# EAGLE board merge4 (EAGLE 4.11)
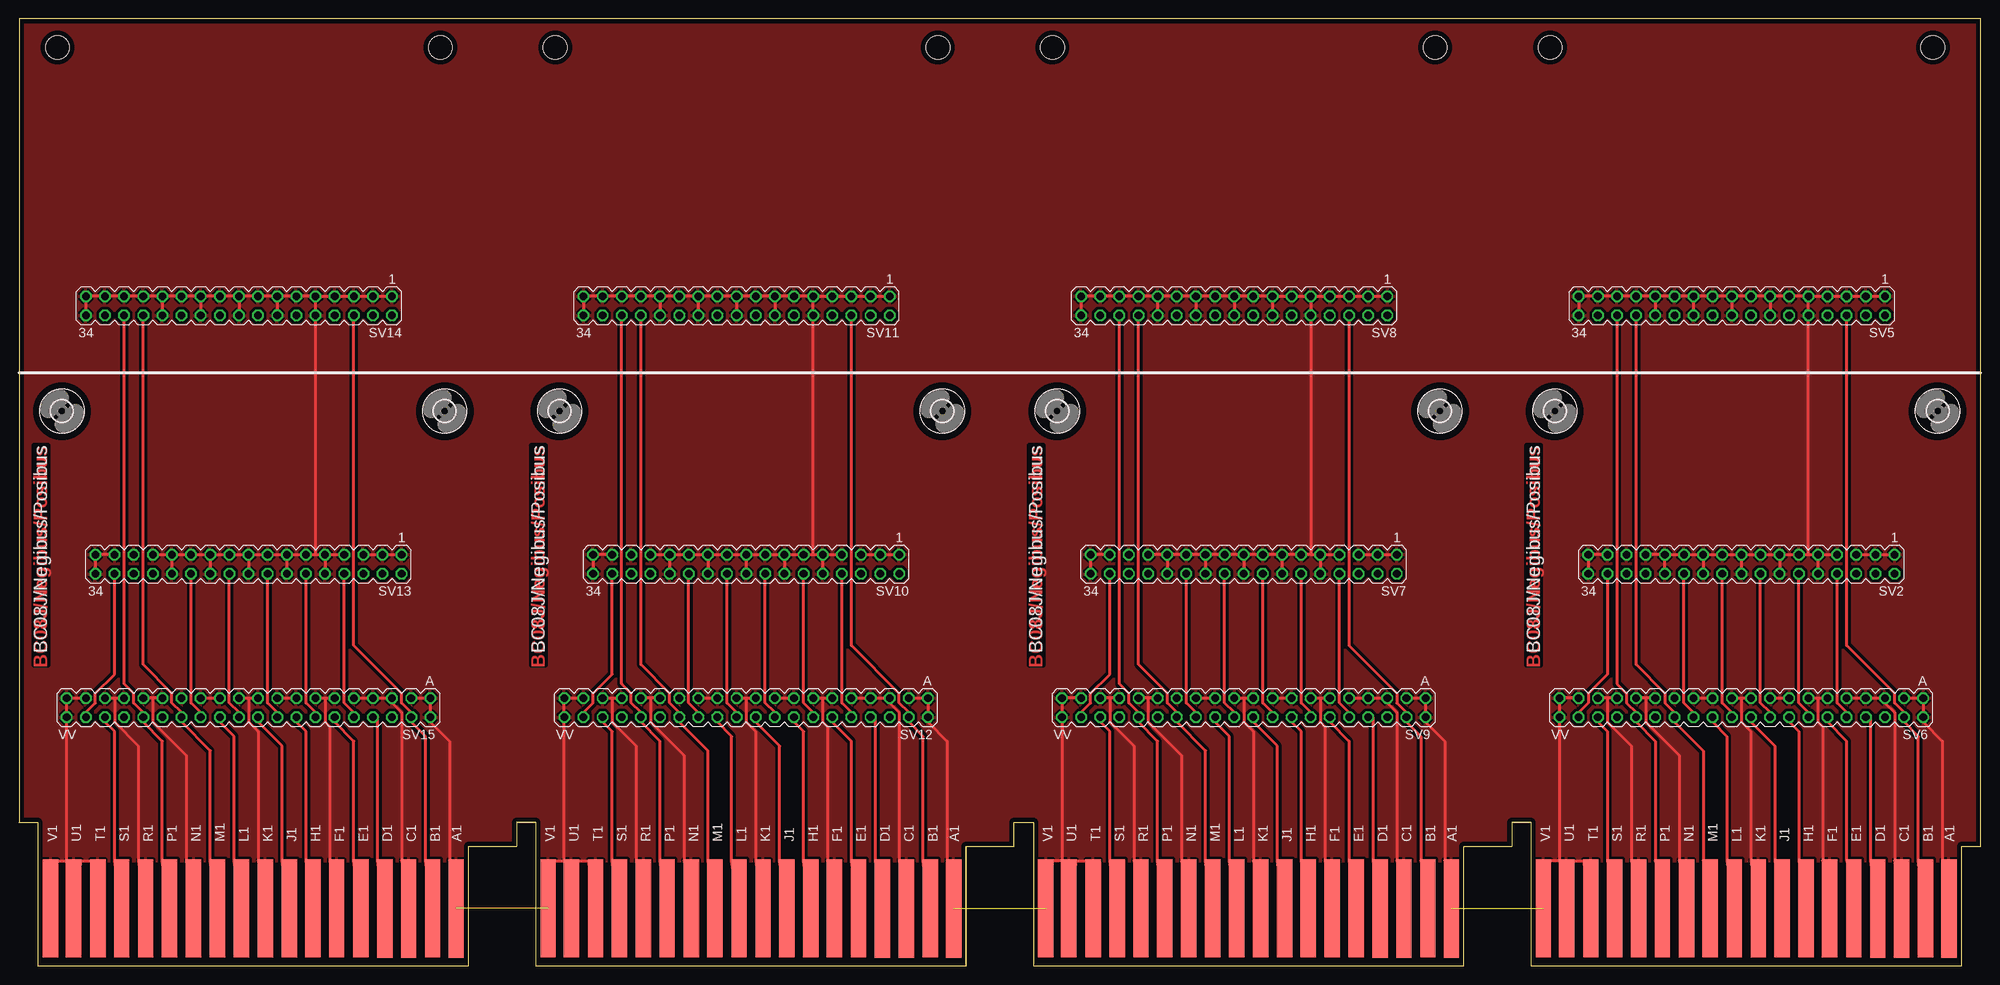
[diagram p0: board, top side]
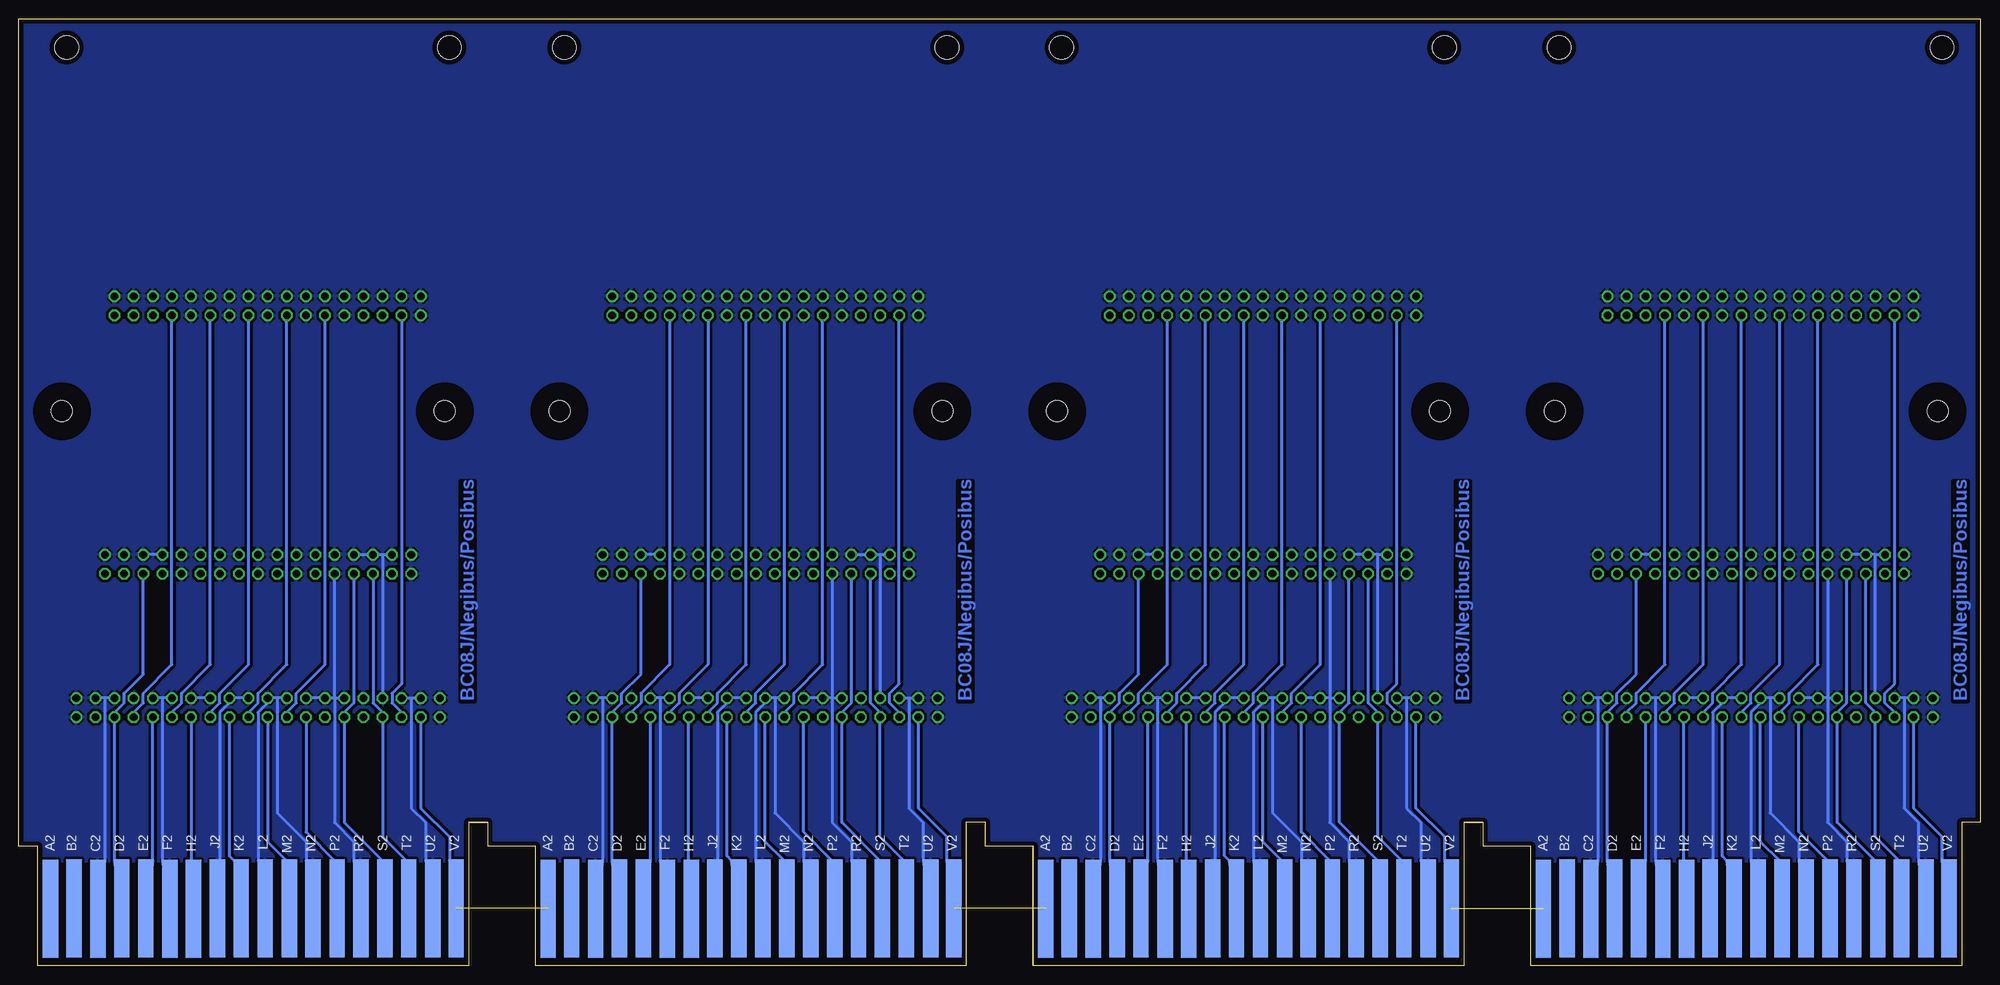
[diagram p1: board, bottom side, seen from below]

Size 260.35 x 125.73 mm. Coordinates in mm from the lower left corner, seen from the top.
Copper layers (1*16): Top 0.035mm / dielectric 1.5mm / Bottom 0.035mm
Design rules "olimex10mil": minimum track width 15mil, minimum drill 24mil, track to track 15mil, track to pad 10mil, pad to pad 10mil, via to via 10mil, smd to smd 10mil, copper to edge 25mil, drill to drill 10mil, minimum pad ring 10mil, minimum via ring 8mil, stop-mask expansion 0mil, vias tented up to drill 0mil, thermal gap 10mil

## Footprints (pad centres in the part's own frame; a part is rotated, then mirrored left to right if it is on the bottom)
MA17-2 = drill 1.016 octagon: 1 -20.32,-1.27; 2 -20.32,1.27; 3 -17.78,-1.27; 4 -17.78,1.27; 5 -15.24,-1.27; 6 -15.24,1.27; 7 -12.7,-1.27; 8 -12.7,1.27; 9 -10.16,-1.27; 10 -10.16,1.27; 11 -7.62,-1.27; 12 -7.62,1.27; 13 -5.08,-1.27; 14 -5.08,1.27; 15 -2.54,-1.27; 16 -2.54,1.27; 17 0,-1.27; 18 0,1.27; 19 2.54,-1.27; 20 2.54,1.27; 21 5.08,-1.27; 22 5.08,1.27; 23 7.62,-1.27; 24 7.62,1.27; 25 10.16,-1.27; 26 10.16,1.27; 27 12.7,-1.27; 28 12.7,1.27; 29 15.24,-1.27; 30 15.24,1.27; 31 17.78,-1.27; 32 17.78,1.27; 33 20.32,-1.27; 34 20.32,1.27
DEC40PIN = drill 1.016 octagon: A -24.13,-1.27; AA 3.81,-1.27; B -24.13,1.27; BB 3.81,1.27; C -21.59,-1.27; CC 6.35,-1.27; D -21.59,1.27; DD 6.35,1.27; E -19.05,-1.27; EE 8.89,-1.27; F -19.05,1.27; FF 8.89,1.27; H -16.51,-1.27; HH 11.43,-1.27; J -16.51,1.27; JJ 11.43,1.27; K -13.97,-1.27; KK 13.97,-1.27; L -13.97,1.27; LL 13.97,1.27; M -11.43,-1.27; MM 16.51,-1.27; N -11.43,1.27; NN 16.51,1.27; P -8.89,-1.27; PP 19.05,-1.27; R -8.89,1.27; RR 19.05,1.27; S -6.35,-1.27; SS 21.59,-1.27; T -6.35,1.27; TT 21.59,1.27; U -3.81,-1.27; UU 24.13,-1.27; V -3.81,1.27; VV 24.13,1.27; W -1.27,-1.27; X -1.27,1.27; Y 1.27,-1.27; Z 1.27,1.27
DECPROTO = hole 3.175: 203.2,121.92; 254,121.92; 187.96,121.92; 137.16,121.92; 71.171,121.92; 121.971,121.92; 55.931,121.92; 5.131,121.92
EDGE-CON2 = smd 13.017 x 2.032: A1 7.633,4.207; B1 7.639,7.327; C1 7.636,10.489; D1 7.633,13.665; E1 7.642,16.84; F1 7.642,20.041; H1 7.642,23.19; J1 7.642,26.34; K1 7.642,29.515; L1 7.642,32.69; M1 7.642,35.89; N1 7.642,39.04; P1 7.642,42.24; R1 7.642,45.39; S1 7.642,48.565; T1 7.642,51.74; U1 7.642,54.966; V1 7.642,58.026 | smd 13.017 x 2.032 bottom: A2 7.614,4.207; B2 7.642,7.328; C2 7.617,10.49; D2 7.642,13.665; E2 7.642,16.84; F2 7.617,20.041; H2 7.617,23.19; J2 7.642,26.34; K2 7.642,29.515; L2 7.642,32.69; M2 7.642,35.89; N2 7.642,39.04; P2 7.642,42.24; R2 7.642,45.39; S2 7.642,48.565; T2 7.642,51.74; U2 7.642,54.966; V2 7.642,58.026
2,8 = hole 2.8: 0,0

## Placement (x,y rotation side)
SV2  [MA17-2]  228.6,53.34 180 top
SV5  [MA17-2]  227.33,87.63 180 top
SV6  [DEC40PIN]  228.6,34.29 180 top
SV7  [MA17-2]  162.56,53.34 180 top
SV8  [MA17-2]  161.29,87.63 180 top
SV9  [DEC40PIN]  162.56,34.29 180 top
SV10  [MA17-2]  96.52,53.34 180 top
SV11  [MA17-2]  95.25,87.63 180 top
SV12  [DEC40PIN]  96.52,34.29 180 top
SV13  [MA17-2]  30.48,53.34 180 top
SV14  [MA17-2]  29.21,87.63 180 top
SV15  [DEC40PIN]  30.48,34.29 180 top
U$5  DECPROTO  [DECPROTO]  0,0 0 top
U$6  [EDGE-CON2]  260.35,0 90 top
U$8  [2,8]  254.63,73.66 270 top
U$9  [2,8]  203.84,73.66 270 top
U$10  [EDGE-CON2]  194.31,0 90 top
U$12  [2,8]  188.59,73.66 270 top
U$13  [2,8]  137.79,73.66 270 top
U$14  [EDGE-CON2]  128.27,0 90 top
U$16  [2,8]  122.56,73.66 270 top
U$17  [2,8]  71.75,73.66 270 top
U$18  [EDGE-CON2]  62.23,0 90 top
U$20  [2,8]  56.52,73.66 270 top
U$21  [2,8]  5.71,73.66 270 top

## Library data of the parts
SV2 SV5 SV7 SV8 SV10 SV11 SV13 SV14 = con-lstb
SV6 SV9 SV12 SV15 U$5 U$6 U$10 U$14 U$18 = dec-con
U$8 U$9 U$12 U$13 U$16 U$17 U$20 U$21 = holes

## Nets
-15V1: U$6.B2
-15V2: U$10.B2
-15V3: U$14.B2
-15V4: U$18.B2
B2: SV5.6 SV6.D U$6.B1
B3: SV8.6 SV9.D U$10.B1
B4: SV11.6 SV12.D U$14.B1
B5: SV14.6 SV15.D U$18.B1
D3: SV2.6 SV6.F U$6.D2
D4: SV5.8 SV6.J U$6.D1
D5: SV7.6 SV9.F U$10.D2
D6: SV8.8 SV9.J U$10.D1
D7: SV10.6 SV12.F U$14.D2
D8: SV11.8 SV12.J U$14.D1
D9: SV13.6 SV15.F U$18.D2
D10: SV14.8 SV15.J U$18.D1
E3: SV2.8 SV6.L U$6.E2
E4: SV5.12 SV6.N U$6.E1
E5: SV7.8 SV9.L U$10.E2
E6: SV8.12 SV9.N U$10.E1
E7: SV10.8 SV12.L U$14.E2
E8: SV11.12 SV12.N U$14.E1
E9: SV13.8 SV15.L U$18.E2
E10: SV14.12 SV15.N U$18.E1
GND: SV2.1 SV2.3 SV2.5 SV2.7 SV2.9 SV2.10 SV2.11 SV2.13 SV2.14 SV2.15 SV2.17 SV2.18 SV2.19 SV2.21 SV2.22 SV2.23 SV2.25 SV2.26 SV2.27 SV2.29 SV2.31 SV2.33 SV2.34 SV5.1 SV5.3 SV5.5 SV5.7 SV5.9 SV5.10 SV5.11 SV5.13 SV5.14 SV5.15 SV5.17 SV5.18 SV5.19 SV5.21 SV5.22 SV5.23 SV5.25 SV5.26 SV5.27 SV5.29 SV5.31 SV5.33 SV5.34 SV6.A SV6.AA SV6.B SV6.C SV6.CC SV6.E SV6.EE SV6.H SV6.HH SV6.K SV6.KK SV6.M SV6.MM SV6.P SV6.PP SV6.S SV6.SS SV6.U SV6.UU SV6.VV SV6.W SV6.Y SV7.1 SV7.3 SV7.5 SV7.7 SV7.9 SV7.10 SV7.11 SV7.13 SV7.14 SV7.15 SV7.17 SV7.18 SV7.19 SV7.21 SV7.22 SV7.23 SV7.25 SV7.26 SV7.27 SV7.29 SV7.31 SV7.33 SV7.34 SV8.1 SV8.3 SV8.5 SV8.7 SV8.9 SV8.10 SV8.11 SV8.13 SV8.14 SV8.15 SV8.17 SV8.18 SV8.19 SV8.21 SV8.22 SV8.23 SV8.25 SV8.26 SV8.27 SV8.29 SV8.31 SV8.33 SV8.34 SV9.A SV9.AA SV9.B SV9.C SV9.CC SV9.E SV9.EE SV9.H SV9.HH SV9.K SV9.KK SV9.M SV9.MM SV9.P SV9.PP SV9.S SV9.SS SV9.U SV9.UU SV9.VV SV9.W SV9.Y SV10.1 SV10.3 SV10.5 SV10.7 SV10.9 SV10.10 SV10.11 SV10.13 SV10.14 SV10.15 SV10.17 SV10.18 SV10.19 SV10.21 SV10.22 SV10.23 SV10.25 SV10.26 SV10.27 SV10.29 SV10.31 SV10.33 SV10.34 SV11.1 SV11.3 SV11.5 SV11.7 SV11.9 SV11.10 SV11.11 SV11.13 SV11.14 SV11.15 SV11.17 SV11.18 SV11.19 SV11.21 SV11.22 SV11.23 SV11.25 SV11.26 SV11.27 SV11.29 SV11.31 SV11.33 SV11.34 SV12.A SV12.AA SV12.B SV12.C SV12.CC SV12.E SV12.EE SV12.H SV12.HH SV12.K SV12.KK SV12.M SV12.MM SV12.P SV12.PP SV12.S SV12.SS SV12.U SV12.UU SV12.VV SV12.W SV12.Y SV13.1 SV13.3 SV13.5 SV13.7 SV13.9 SV13.10 SV13.11 SV13.13 SV13.14 SV13.15 SV13.17 SV13.18 SV13.19 SV13.21 SV13.22 SV13.23 SV13.25 SV13.26 SV13.27 SV13.29 SV13.31 SV13.33 SV13.34 SV14.1 SV14.3 SV14.5 SV14.7 SV14.9 SV14.10 SV14.11 SV14.13 SV14.14 SV14.15 SV14.17 SV14.18 SV14.19 SV14.21 SV14.22 SV14.23 SV14.25 SV14.26 SV14.27 SV14.29 SV14.31 SV14.33 SV14.34 SV15.A SV15.AA SV15.B SV15.C SV15.CC SV15.E SV15.EE SV15.H SV15.HH SV15.K SV15.KK SV15.M SV15.MM SV15.P SV15.PP SV15.S SV15.SS SV15.U SV15.UU SV15.VV SV15.W SV15.Y U$6.A1 U$6.C1 U$6.C2 U$6.F1 U$6.F2 U$6.J2 U$6.K1 U$6.L2 U$6.N1 U$6.N2 U$6.R1 U$6.R2 U$6.T1 U$6.U1 U$6.U2 U$6.V1 U$10.A1 U$10.C1 U$10.C2 U$10.F1 U$10.F2 U$10.J2 U$10.K1 U$10.L2 U$10.N1 U$10.N2 U$10.R1 U$10.R2 U$10.T1 U$10.U1 U$10.U2 U$10.V1 U$14.A1 U$14.C1 U$14.C2 U$14.F1 U$14.F2 U$14.J2 U$14.K1 U$14.L2 U$14.N1 U$14.N2 U$14.R1 U$14.R2 U$14.T1 U$14.U1 U$14.U2 U$14.V1 U$18.A1 U$18.C1 U$18.C2 U$18.F1 U$18.F2 U$18.J2 U$18.K1 U$18.L2 U$18.N1 U$18.N2 U$18.R1 U$18.R2 U$18.T1 U$18.U1 U$18.U2 U$18.V1
H3: SV2.12 SV6.R U$6.H2
H4: SV5.16 SV6.T U$6.H1
H5: SV7.12 SV9.R U$10.H2
H6: SV8.16 SV9.T U$10.H1
H7: SV10.12 SV12.R U$14.H2
H8: SV11.16 SV12.T U$14.H1
H9: SV13.12 SV15.R U$18.H2
H10: SV14.16 SV15.T U$18.H1
J2: SV5.20 SV6.X U$6.J1
J3: SV8.20 SV9.X U$10.J1
J4: SV11.20 SV12.X U$14.J1
J5: SV14.20 SV15.X U$18.J1
K1: SV2.16 SV6.V U$6.K2
K3: SV7.16 SV9.V U$10.K2
K4: SV10.16 SV12.V U$14.K2
K5: SV13.16 SV15.V U$18.K2
L2: SV5.24 SV6.BB U$6.L1
L3: SV8.24 SV9.BB U$10.L1
L4: SV11.24 SV12.BB U$14.L1
L5: SV14.24 SV15.BB U$18.L1
M3: SV2.20 SV6.Z U$6.M2
M4: SV5.28 SV6.FF U$6.M1
M5: SV7.20 SV9.Z U$10.M2
M6: SV8.28 SV9.FF U$10.M1
M7: SV10.20 SV12.Z U$14.M2
M8: SV11.28 SV12.FF U$14.M1
M9: SV13.20 SV15.Z U$18.M2
M10: SV14.28 SV15.FF U$18.M1
P3: SV2.24 SV6.DD U$6.P2
P4: SV5.30 SV6.LL U$6.P1
P5: SV7.24 SV9.DD U$10.P2
P6: SV8.30 SV9.LL U$10.P1
P7: SV10.24 SV12.DD U$14.P2
P8: SV11.30 SV12.LL U$14.P1
P9: SV13.24 SV15.DD U$18.P2
P10: SV14.30 SV15.LL U$18.P1
S3: SV2.28 SV6.JJ U$6.S2
S4: SV5.32 SV6.RR U$6.S1
S5: SV7.28 SV9.JJ U$10.S2
S6: SV8.32 SV9.RR U$10.S1
S7: SV10.28 SV12.JJ U$14.S2
S8: SV11.32 SV12.RR U$14.S1
S9: SV13.28 SV15.JJ U$18.S2
S10: SV14.32 SV15.RR U$18.S1
T1: SV2.30 SV6.NN U$6.T2
T3: SV7.30 SV9.NN U$10.T2
T4: SV10.30 SV12.NN U$14.T2
T5: SV13.30 SV15.NN U$18.T2
V1: SV2.32 SV6.TT U$6.V2
V3: SV7.32 SV9.TT U$10.V2
V4: SV10.32 SV12.TT U$14.V2
V5: SV13.32 SV15.TT U$18.V2
VCC1: U$6.A2
VCC2: U$10.A2
VCC3: U$14.A2
VCC4: U$18.A2

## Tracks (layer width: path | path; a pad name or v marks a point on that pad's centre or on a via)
B2
  Top 0.381: SV5.6 242.57,85.73 242.57,42.55 248.92,36.2 248.92,34.93 250.19,33.66 SV6.D 250.19,32.39 252.09,30.48 252.09,13.97 U$6.B1
B3
  Top 0.381: SV8.6 176.53,85.73 176.53,42.55 182.88,36.2 182.88,34.93 184.15,33.66 SV9.D 184.15,32.39 186.06,30.48 186.06,13.97 U$10.B1
B4
  Top 0.381: SV11.6 110.49,85.73 110.49,42.55 116.84,36.2 116.84,34.93 118.11,33.66 SV12.D 118.11,32.39 120.02,30.48 120.02,13.97 U$14.B1
B5
  Top 0.381: SV14.6 44.45,85.73 44.45,42.55 50.8,36.2 50.8,34.93 52.07,33.66 SV15.D 52.07,32.39 53.98,30.48 53.98,13.97 U$18.B1
D3
  Bottom 0.381: SV2.6 243.84,51.44 243.84,38.74 246.38,36.2 246.38,34.93 247.65,33.66 SV6.F 247.65,32.39 247.65,13.97 U$6.D2
D4
  Top 0.381: U$6.D1 245.75,13.97 245.75,33.02 SV6.J
  Bottom 0.381: SV5.8 240.03,85.73 240.03,40.01 243.84,36.2 243.84,34.93 245.11,33.66 SV6.J
D5
  Bottom 0.381: SV7.6 177.8,51.44 177.8,38.74 180.34,36.2 180.34,34.93 181.61,33.66 SV9.F 181.61,32.39 181.61,13.97 U$10.D2
D6
  Top 0.381: U$10.D1 179.71,13.97 179.71,33.02 SV9.J
  Bottom 0.381: SV8.8 173.99,85.73 173.99,40.01 177.8,36.2 177.8,34.93 179.07,33.66 SV9.J
D7
  Bottom 0.381: SV10.6 111.76,51.44 111.76,38.74 114.3,36.2 114.3,34.93 115.57,33.66 SV12.F 115.57,32.39 115.57,13.97 U$14.D2
D8
  Top 0.381: U$14.D1 113.67,13.97 113.67,33.02 SV12.J
  Bottom 0.381: SV11.8 107.95,85.73 107.95,40.01 111.76,36.2 111.76,34.93 113.03,33.66 SV12.J
D9
  Bottom 0.381: SV13.6 45.72,51.44 45.72,38.74 48.26,36.2 48.26,34.93 49.53,33.66 SV15.F 49.53,32.39 49.53,13.97 U$18.D2
D10
  Top 0.381: U$18.D1 47.62,13.97 47.62,33.02 SV15.J
  Bottom 0.381: SV14.8 41.91,85.73 41.91,40.01 45.72,36.2 45.72,34.93 46.99,33.66 SV15.J
E3
  Top 0.381: SV2.8 241.3,51.44 241.3,34.93 242.57,33.66 SV6.L
  Bottom 0.381: SV6.L 242.57,32.39 242.57,13.97 U$6.E2
E4
  Top 0.381: U$6.E1 242.57,13.97 242.57,29.85 240.03,32.39 SV6.N
  Bottom 0.381: SV5.12 234.95,85.73 234.95,40.01 238.76,36.2 238.76,34.93 240.03,33.66 SV6.N
E5
  Top 0.381: SV7.8 175.26,51.44 175.26,34.93 176.53,33.66 SV9.L
  Bottom 0.381: SV9.L 176.53,32.39 176.53,13.97 U$10.E2
E6
  Top 0.381: U$10.E1 176.53,13.97 176.53,29.85 173.99,32.39 SV9.N
  Bottom 0.381: SV8.12 168.91,85.73 168.91,40.01 172.72,36.2 172.72,34.93 173.99,33.66 SV9.N
E7
  Top 0.381: SV10.8 109.22,51.44 109.22,34.93 110.49,33.66 SV12.L
  Bottom 0.381: SV12.L 110.49,32.39 110.49,13.97 U$14.E2
E8
  Top 0.381: U$14.E1 110.49,13.97 110.49,29.85 107.95,32.39 SV12.N
  Bottom 0.381: SV11.12 102.87,85.73 102.87,40.01 106.68,36.2 106.68,34.93 107.95,33.66 SV12.N
E9
  Top 0.381: SV13.8 43.18,51.44 43.18,34.93 44.45,33.66 SV15.L
  Bottom 0.381: SV15.L 44.45,32.39 44.45,13.97 U$18.E2
E10
  Top 0.381: U$18.E1 44.45,13.97 44.45,29.85 41.91,32.39 SV15.N
  Bottom 0.381: SV14.12 36.83,85.73 36.83,40.01 40.64,36.2 40.64,34.93 41.91,33.66 SV15.N
GND  (3 unrouted)
  Top 0.381: 17.78,35.56 18.41,35.56 SV15.HH | 17.78,35.56 17.14,35.56 SV15.KK | SV15.AA 26.04,35.56 24.77,35.56 SV15.CC | 30.48,35.56 29.84,35.56 SV15.Y | 30.48,35.56 31.11,35.56 SV15.W | SV15.S 36.2,35.56 34.92,35.56 SV15.U | 40.64,35.56 40.01,35.56 SV15.P | 40.64,35.56 41.27,35.56 SV15.M | SV15.K 45.09,35.56 46.35,35.56 SV15.H 47.62,35.56 48.9,35.56 SV15.E 49.53,34.93 50.8,33.66 50.8,13.97 U$18.C1 | SV15.C 52.7,35.56 53.98,35.56 SV15.A 54.61,34.93 54.61,33.66 SV15.B 54.61,32.39 57.15,29.85 57.15,13.97 U$18.A1 | 17.78,35.56 17.78,32.39 22.23,27.94 22.23,13.97 U$18.N1 | 30.48,35.56 30.48,32.39 31.75,31.12 31.75,13.97 U$18.K1 | 40.64,35.56 40.64,32.39 41.27,31.75 41.27,13.97 U$18.F1 | SV14.34 8.89,87 8.89,88.27 SV14.33 9.53,88.9 10.79,88.9 SV14.31 12.06,88.9 13.34,88.9 SV14.29 14.61,88.9 15.88,88.9 SV14.27 17.14,88.9 18.41,88.9 SV14.25 | SV14.26 19.05,87 19.05,88.27 SV14.25 | SV14.25 19.68,88.9 20.95,88.9 SV14.23 22.23,88.9 23.5,88.9 SV14.21 | SV14.22 24.13,87 24.13,88.27 SV14.21 | SV14.21 24.77,88.9 26.04,88.9 SV14.19 27.3,88.9 28.57,88.9 SV14.17 | SV14.18 29.21,87 29.21,88.27 SV14.17 | SV14.17 29.84,88.9 31.11,88.9 SV14.15 32.38,88.9 33.66,88.9 SV14.13 | SV14.14 34.29,87 34.29,88.27 SV14.13 | SV14.13 34.92,88.9 36.2,88.9 SV14.11 37.47,88.9 38.73,88.9 SV14.9 | SV14.9 39.37,88.27 39.37,87 SV14.10 39.37,85.73 39.37,54.61 | SV14.9 40.01,88.9 41.27,88.9 SV14.7 42.55,88.9 43.81,88.9 SV14.5 45.09,88.9 46.35,88.9 SV14.3 47.62,88.9 48.9,88.9 SV14.1 | 6.35,13.97 5.08,13.97 U$18.V1 | 6.35,13.97 U$18.U1 | U$18.T1 9.53,13.97 8.26,13.97 U$18.U1 | SV15.SS 8.26,35.56 6.99,35.56 SV15.UU 6.35,34.93 6.35,33.66 SV15.VV 6.35,32.39 6.35,13.97
  Top 0.381: 12.7,35.56 12.06,35.56 SV15.PP | 12.7,35.56 13.34,35.56 SV15.MM | SV13.34 10.16,52.71 10.16,53.98 SV13.33 10.79,54.61 12.06,54.61 SV13.31 | SV13.25 19.68,54.61 18.41,54.61 SV13.27 | SV13.25 20.95,54.61 22.23,54.61 SV13.23 23.5,54.61 24.77,54.61 SV13.21 | SV13.26 20.32,52.71 20.32,53.98 SV13.25 | SV13.22 25.4,52.71 25.4,53.98 SV13.21 | SV13.21 26.04,54.61 27.3,54.61 SV13.19 28.57,54.61 29.84,54.61 SV13.17 | SV13.17 31.11,54.61 32.38,54.61 SV13.15 33.66,54.61 34.92,54.61 SV13.13 | SV13.18 30.48,52.71 30.48,53.98 SV13.17 | SV13.14 35.56,52.71 35.56,53.98 SV13.13 | SV13.13 36.2,54.61 37.47,54.61 SV13.11 38.73,54.61 39.37,54.61 | 39.37,54.61 40.01,54.61 SV13.9 | SV13.10 40.64,52.71 40.64,53.98 SV13.9 | SV13.7 42.55,54.61 41.27,54.61 SV13.9 | SV13.5 46.35,54.61 47.62,54.61 SV13.3 48.9,54.61 50.16,54.61 SV13.1 | 12.7,35.56 12.7,32.39 15.88,29.21 15.88,13.97 U$18.R1 | 6.35,13.97 U$18.U1 | 83.82,35.56 84.45,35.56 SV12.HH | 83.82,35.56 83.19,35.56 SV12.KK | SV12.AA 92.08,35.56 90.81,35.56 SV12.CC | 96.52,35.56 95.89,35.56 SV12.Y | 96.52,35.56 97.16,35.56 SV12.W | SV12.S 102.23,35.56 100.97,35.56 SV12.U | 106.68,35.56 106.05,35.56 SV12.P | 106.68,35.56 107.31,35.56 SV12.M | SV12.K 111.12,35.56 112.39,35.56 SV12.H 113.67,35.56 114.94,35.56 SV12.E 115.57,34.93 116.84,33.66 116.84,13.97 U$14.C1 | SV12.C 118.75,35.56 120.02,35.56 SV12.A 120.65,34.93 120.65,33.66 SV12.B 120.65,32.39 123.19,29.85 123.19,13.97 U$14.A1 | 83.82,35.56 83.82,32.39 88.27,27.94 88.27,13.97 U$14.N1 | 96.52,35.56 96.52,32.39 97.79,31.12 97.79,13.97 U$14.K1 | 106.68,35.56 106.68,32.39 107.31,31.75 107.31,13.97 U$14.F1
  Top 0.381: SV11.34 74.93,87 74.93,88.27 SV11.33 75.56,88.9 76.83,88.9 SV11.31 78.11,88.9 79.38,88.9 SV11.29 80.64,88.9 81.92,88.9 SV11.27 83.19,88.9 84.45,88.9 SV11.25 | SV11.26 85.09,87 85.09,88.27 SV11.25 | SV11.25 85.72,88.9 87,88.9 SV11.23 88.27,88.9 89.53,88.9 SV11.21 | SV11.22 90.17,87 90.17,88.27 SV11.21 | SV11.21 90.81,88.9 92.08,88.9 SV11.19 93.34,88.9 94.61,88.9 SV11.17 | SV11.18 95.25,87 95.25,88.27 SV11.17 | SV11.17 95.89,88.9 97.16,88.9 SV11.15 98.42,88.9 99.69,88.9 SV11.13 | SV11.14 100.33,87 100.33,88.27 SV11.13 | SV11.13 100.97,88.9 102.23,88.9 SV11.11 103.5,88.9 104.78,88.9 SV11.9 | SV11.9 105.41,88.27 105.41,87 SV11.10 105.41,85.73 105.41,54.61 | SV11.9 106.05,88.9 107.31,88.9 SV11.7 108.58,88.9 109.86,88.9 SV11.5 111.12,88.9 112.39,88.9 SV11.3 113.67,88.9 114.94,88.9 SV11.1 | 72.39,13.97 71.12,13.97 U$14.V1 | 72.39,13.97 U$14.U1 | U$14.T1 75.56,13.97 74.3,13.97 U$14.U1 | SV12.SS 74.3,35.56 73.03,35.56 SV12.UU 72.39,34.93 72.39,33.66 SV12.VV 72.39,32.39 72.39,13.97 | 78.74,35.56 78.11,35.56 SV12.PP | 78.74,35.56 79.38,35.56 SV12.MM | SV10.34 76.2,52.71 76.2,53.98 SV10.33 76.83,54.61 78.11,54.61 SV10.31 | SV10.25 85.72,54.61 84.45,54.61 SV10.27 | SV10.25 87,54.61 88.27,54.61 SV10.23 89.53,54.61 90.81,54.61 SV10.21 | SV10.26 86.36,52.71 86.36,53.98 SV10.25 | SV10.22 91.44,52.71 91.44,53.98 SV10.21 | SV10.21 92.08,54.61 93.34,54.61 SV10.19 94.61,54.61 95.89,54.61 SV10.17 | SV10.17 97.16,54.61 98.42,54.61 SV10.15 99.69,54.61 100.97,54.61 SV10.13 | SV10.18 96.52,52.71 96.52,53.98 SV10.17 | SV10.14 101.6,52.71 101.6,53.98 SV10.13 | SV10.13 102.23,54.61 103.5,54.61 SV10.11 104.78,54.61 105.41,54.61
  Top 0.381: 105.41,54.61 106.05,54.61 SV10.9 | SV10.10 106.68,52.71 106.68,53.98 SV10.9 | SV10.7 108.58,54.61 107.31,54.61 SV10.9 | SV10.5 112.39,54.61 113.67,54.61 SV10.3 114.94,54.61 116.2,54.61 SV10.1 | 78.74,35.56 78.74,32.39 81.92,29.21 81.92,13.97 U$14.R1 | 72.39,13.97 U$14.U1 | 149.86,35.56 150.5,35.56 SV9.HH | 149.86,35.56 149.22,35.56 SV9.KK | SV9.AA 158.12,35.56 156.84,35.56 SV9.CC | 162.56,35.56 161.93,35.56 SV9.Y | 162.56,35.56 163.19,35.56 SV9.W | SV9.S 168.28,35.56 167,35.56 SV9.U | 172.72,35.56 172.09,35.56 SV9.P | 172.72,35.56 173.35,35.56 SV9.M | SV9.K 177.16,35.56 178.44,35.56 SV9.H 179.71,35.56 180.97,35.56 SV9.E 181.61,34.93 182.88,33.66 182.88,13.97 U$10.C1 | SV9.C 184.78,35.56 186.06,35.56 SV9.A 186.69,34.93 186.69,33.66 SV9.B 186.69,32.39 189.23,29.85 189.23,13.97 U$10.A1 | 149.86,35.56 149.86,32.39 154.31,27.94 154.31,13.97 U$10.N1 | 162.56,35.56 162.56,32.39 163.83,31.12 163.83,13.97 U$10.K1 | 172.72,35.56 172.72,32.39 173.35,31.75 173.35,13.97 U$10.F1 | SV8.34 140.97,87 140.97,88.27 SV8.33 141.6,88.9 142.88,88.9 SV8.31 144.15,88.9 145.41,88.9 SV8.29 146.69,88.9 147.96,88.9 SV8.27 149.22,88.9 150.5,88.9 SV8.25 | SV8.26 151.13,87 151.13,88.27 SV8.25 | SV8.25 151.76,88.9 153.03,88.9 SV8.23 154.31,88.9 155.57,88.9 SV8.21 | SV8.22 156.21,87 156.21,88.27 SV8.21 | SV8.21 156.84,88.9 158.12,88.9 SV8.19 159.38,88.9 160.66,88.9 SV8.17 | SV8.18 161.29,87 161.29,88.27 SV8.17 | SV8.17 161.93,88.9 163.19,88.9 SV8.15 164.47,88.9 165.74,88.9 SV8.13 | SV8.14 166.37,87 166.37,88.27 SV8.13 | SV8.13 167,88.9 168.28,88.9 SV8.11 169.54,88.9 170.81,88.9 SV8.9 | SV8.9 171.45,88.27 171.45,87 SV8.10 171.45,85.73 171.45,54.61
  Top 0.381: SV8.9 172.09,88.9 173.35,88.9 SV8.7 174.62,88.9 175.9,88.9 SV8.5 177.16,88.9 178.44,88.9 SV8.3 179.71,88.9 180.97,88.9 SV8.1 | 138.43,13.97 137.16,13.97 U$10.V1 | 138.43,13.97 U$10.U1 | U$10.T1 141.6,13.97 140.34,13.97 U$10.U1 | SV9.SS 140.34,35.56 139.06,35.56 SV9.UU 138.43,34.93 138.43,33.66 SV9.VV 138.43,32.39 138.43,13.97 | 144.78,35.56 144.15,35.56 SV9.PP | 144.78,35.56 145.41,35.56 SV9.MM | SV7.34 142.24,52.71 142.24,53.98 SV7.33 142.88,54.61 144.15,54.61 SV7.31 | SV7.25 151.76,54.61 150.5,54.61 SV7.27 | SV7.25 153.03,54.61 154.31,54.61 SV7.23 155.57,54.61 156.84,54.61 SV7.21 | SV7.26 152.4,52.71 152.4,53.98 SV7.25 | SV7.22 157.48,52.71 157.48,53.98 SV7.21 | SV7.21 158.12,54.61 159.38,54.61 SV7.19 160.66,54.61 161.93,54.61 SV7.17 | SV7.17 163.19,54.61 164.47,54.61 SV7.15 165.74,54.61 167,54.61 SV7.13 | SV7.18 162.56,52.71 162.56,53.98 SV7.17 | SV7.14 167.64,52.71 167.64,53.98 SV7.13 | SV7.13 168.28,54.61 169.54,54.61 SV7.11 170.81,54.61 171.45,54.61 | 171.45,54.61 172.09,54.61 SV7.9 | SV7.10 172.72,52.71 172.72,53.98 SV7.9 | SV7.7 174.62,54.61 173.35,54.61 SV7.9 | SV7.5 178.44,54.61 179.71,54.61 SV7.3 180.97,54.61 182.25,54.61 SV7.1 | 144.78,35.56 144.78,32.39 147.96,29.21 147.96,13.97 U$10.R1 | 138.43,13.97 U$10.U1 | 215.9,35.56 216.53,35.56 SV6.HH | 215.9,35.56 215.26,35.56 SV6.KK | SV6.AA 224.16,35.56 222.88,35.56 SV6.CC | 228.6,35.56 227.97,35.56 SV6.Y | 228.6,35.56 229.24,35.56 SV6.W | SV6.S 234.31,35.56 233.04,35.56 SV6.U | 238.76,35.56 238.12,35.56 SV6.P | 238.76,35.56 239.4,35.56 SV6.M | SV6.K 243.21,35.56 244.47,35.56 SV6.H 245.75,35.56 247.01,35.56 SV6.E 247.65,34.93 248.92,33.66 248.92,13.97 U$6.C1
  Top 0.381: SV6.C 250.82,35.56 252.09,35.56 SV6.A 252.73,34.93 252.73,33.66 SV6.B 252.73,32.39 255.27,29.85 255.27,13.97 U$6.A1 | 215.9,35.56 215.9,32.39 220.34,27.94 220.34,13.97 U$6.N1 | 228.6,35.56 228.6,32.39 229.87,31.12 229.87,13.97 U$6.K1 | 238.76,35.56 238.76,32.39 239.4,31.75 239.4,13.97 U$6.F1 | SV5.34 207.01,87 207.01,88.27 SV5.33 207.65,88.9 208.91,88.9 SV5.31 210.19,88.9 211.46,88.9 SV5.29 212.72,88.9 214,88.9 SV5.27 215.26,88.9 216.53,88.9 SV5.25 | SV5.26 217.17,87 217.17,88.27 SV5.25 | SV5.25 217.81,88.9 219.07,88.9 SV5.23 220.34,88.9 221.62,88.9 SV5.21 | SV5.22 222.25,87 222.25,88.27 SV5.21 | SV5.21 222.88,88.9 224.16,88.9 SV5.19 225.43,88.9 226.69,88.9 SV5.17 | SV5.18 227.33,87 227.33,88.27 SV5.17 | SV5.17 227.97,88.9 229.24,88.9 SV5.15 230.5,88.9 231.78,88.9 SV5.13 | SV5.14 232.41,87 232.41,88.27 SV5.13 | SV5.13 233.04,88.9 234.31,88.9 SV5.11 235.59,88.9 236.85,88.9 SV5.9 | SV5.9 237.49,88.27 237.49,87 SV5.10 237.49,85.73 237.49,54.61 | SV5.9 238.12,88.9 239.4,88.9 SV5.7 240.66,88.9 241.94,88.9 SV5.5 243.21,88.9 244.47,88.9 SV5.3 245.75,88.9 247.01,88.9 SV5.1 | 204.47,13.97 203.2,13.97 U$6.V1 | 204.47,13.97 U$6.U1 | U$6.T1 207.65,13.97 206.38,13.97 U$6.U1 | SV6.SS 206.38,35.56 205.1,35.56 SV6.UU 204.47,34.93 204.47,33.66 SV6.VV 204.47,32.39 204.47,13.97 | 210.82,35.56 210.19,35.56 SV6.PP | 210.82,35.56 211.46,35.56 SV6.MM | SV2.34 208.28,52.71 208.28,53.98 SV2.33 208.91,54.61 210.19,54.61 SV2.31 | SV2.25 217.81,54.61 216.53,54.61 SV2.27 | SV2.25 219.07,54.61 220.34,54.61 SV2.23 221.62,54.61 222.88,54.61 SV2.21 | SV2.26 218.44,52.71 218.44,53.98 SV2.25
  Top 0.381: SV2.22 223.52,52.71 223.52,53.98 SV2.21 | SV2.21 224.16,54.61 225.43,54.61 SV2.19 226.69,54.61 227.97,54.61 SV2.17 | SV2.17 229.24,54.61 230.5,54.61 SV2.15 231.78,54.61 233.04,54.61 SV2.13 | SV2.18 228.6,52.71 228.6,53.98 SV2.17 | SV2.14 233.68,52.71 233.68,53.98 SV2.13 | SV2.13 234.31,54.61 235.59,54.61 SV2.11 236.85,54.61 237.49,54.61 | 237.49,54.61 238.12,54.61 SV2.9 | SV2.10 238.76,52.71 238.76,53.98 SV2.9 | SV2.7 240.66,54.61 239.4,54.61 SV2.9 | SV2.5 244.47,54.61 245.75,54.61 SV2.3 247.01,54.61 248.28,54.61 SV2.1 | 210.82,35.56 210.82,32.39 214,29.21 214,13.97 U$6.R1 | 204.47,13.97 U$6.U1
  Bottom 0.381: 20.32,35.56 19.68,35.56 SV15.HH | 20.32,35.56 20.95,35.56 SV15.EE 22.23,35.56 23.5,35.56 SV15.CC | 27.94,35.56 27.3,35.56 SV15.AA | 27.94,35.56 28.57,35.56 SV15.Y 29.21,34.93 30.48,33.66 30.48,13.97 U$18.L2 | SV15.W 32.38,35.56 33.66,35.56 SV15.U 34.29,34.93 35.56,33.66 35.56,13.97 U$18.J2 | SV15.P 38.73,35.56 37.47,35.56 SV15.S | 43.18,35.56 42.55,35.56 SV15.M | 43.18,35.56 43.81,35.56 SV15.K | 50.8,35.56 50.16,35.56 SV15.E | 50.8,35.56 51.44,35.56 SV15.C | 20.32,35.56 20.32,19.05 17.78,16.51 17.78,13.97 U$18.R1 | 27.94,35.56 27.94,20.32 24.13,16.51 24.13,13.97 U$18.N1 | 43.18,35.56 43.18,13.97 U$18.F2 | 50.8,35.56 50.8,13.97 U$18.C2 | 10.16,35.56 10.79,35.56 SV15.PP | 10.16,35.56 9.53,35.56 SV15.SS | 13.97,54.61 13.34,54.61 SV13.31 | 13.97,54.61 14.61,54.61 SV13.29 15.88,54.61 17.14,54.61 SV13.27 | SV13.5 45.09,54.61 43.81,54.61 SV13.7 | 13.97,54.61 13.97,36.2 SV15.MM | 20.32,35.56 20.32,51.44 SV13.26 | 10.16,35.56 10.16,20.96 8.26,19.05 8.26,13.97 U$18.U1 | 86.36,35.56 85.72,35.56 SV12.HH | 86.36,35.56 87,35.56 SV12.EE 88.27,35.56 89.53,35.56 SV12.CC | 93.98,35.56 93.34,35.56 SV12.AA | 93.98,35.56 94.61,35.56 SV12.Y 95.25,34.93 96.52,33.66 96.52,13.97 U$14.L2 | SV12.W 98.42,35.56 99.69,35.56 SV12.U 100.33,34.93 101.6,33.66 101.6,13.97 U$14.J2 | SV12.P 104.78,35.56 103.5,35.56 SV12.S | 109.22,35.56 108.58,35.56 SV12.M | 109.22,35.56 109.86,35.56 SV12.K | 116.84,35.56 116.2,35.56 SV12.E | 116.84,35.56 117.47,35.56 SV12.C | 86.36,35.56 86.36,19.05 83.82,16.51 83.82,13.97 U$14.R1 | 93.98,35.56 93.98,20.32 90.17,16.51 90.17,13.97 U$14.N1 | 109.22,35.56 109.22,13.97 U$14.F2 | 116.84,35.56 116.84,13.97 U$14.C2
  Bottom 0.381: 76.2,35.56 76.83,35.56 SV12.PP | 76.2,35.56 75.56,35.56 SV12.SS | 80.01,54.61 79.38,54.61 SV10.31 | 80.01,54.61 80.64,54.61 SV10.29 81.92,54.61 83.19,54.61 SV10.27 | SV10.5 111.12,54.61 109.86,54.61 SV10.7 | 80.01,54.61 80.01,36.2 SV12.MM | 86.36,35.56 86.36,51.44 SV10.26 | 76.2,35.56 76.2,20.96 74.3,19.05 74.3,13.97 U$14.U1 | 152.4,35.56 151.76,35.56 SV9.HH | 152.4,35.56 153.03,35.56 SV9.EE 154.31,35.56 155.57,35.56 SV9.CC | 160.02,35.56 159.38,35.56 SV9.AA | 160.02,35.56 160.66,35.56 SV9.Y 161.29,34.93 162.56,33.66 162.56,13.97 U$10.L2 | SV9.W 164.47,35.56 165.74,35.56 SV9.U 166.37,34.93 167.64,33.66 167.64,13.97 U$10.J2 | SV9.P 170.81,35.56 169.54,35.56 SV9.S | 175.26,35.56 174.62,35.56 SV9.M | 175.26,35.56 175.9,35.56 SV9.K | 182.88,35.56 182.25,35.56 SV9.E | 182.88,35.56 183.51,35.56 SV9.C | 152.4,35.56 152.4,19.05 149.86,16.51 149.86,13.97 U$10.R1 | 160.02,35.56 160.02,20.32 156.21,16.51 156.21,13.97 U$10.N1 | 175.26,35.56 175.26,13.97 U$10.F2 | 182.88,35.56 182.88,13.97 U$10.C2 | 142.24,35.56 142.88,35.56 SV9.PP | 142.24,35.56 141.6,35.56 SV9.SS | 146.05,54.61 145.41,54.61 SV7.31 | 146.05,54.61 146.69,54.61 SV7.29 147.96,54.61 149.22,54.61 SV7.27 | SV7.5 177.16,54.61 175.9,54.61 SV7.7 | 146.05,54.61 146.05,36.2 SV9.MM | 152.4,35.56 152.4,51.44 SV7.26 | 142.24,35.56 142.24,20.96 140.34,19.05 140.34,13.97 U$10.U1 | 218.44,35.56 217.81,35.56 SV6.HH | 218.44,35.56 219.07,35.56 SV6.EE 220.34,35.56 221.62,35.56 SV6.CC | 226.06,35.56 225.43,35.56 SV6.AA | 226.06,35.56 226.69,35.56 SV6.Y 227.33,34.93 228.6,33.66 228.6,13.97 U$6.L2 | SV6.W 230.5,35.56 231.78,35.56 SV6.U 232.41,34.93 233.68,33.66 233.68,13.97 U$6.J2
  Bottom 0.381: SV6.P 236.85,35.56 235.59,35.56 SV6.S | 241.3,35.56 240.66,35.56 SV6.M | 241.3,35.56 241.94,35.56 SV6.K | 248.92,35.56 248.28,35.56 SV6.E | 248.92,35.56 249.56,35.56 SV6.C | 218.44,35.56 218.44,19.05 215.9,16.51 215.9,13.97 U$6.R1 | 226.06,35.56 226.06,20.32 222.25,16.51 222.25,13.97 U$6.N1 | 241.3,35.56 241.3,13.97 U$6.F2 | 248.92,35.56 248.92,13.97 U$6.C2 | 208.28,35.56 208.91,35.56 SV6.PP | 208.28,35.56 207.65,35.56 SV6.SS | 212.09,54.61 211.46,54.61 SV2.31 | 212.09,54.61 212.72,54.61 SV2.29 214,54.61 215.26,54.61 SV2.27 | SV2.5 243.21,54.61 241.94,54.61 SV2.7 | 212.09,54.61 212.09,36.2 SV6.MM | 218.44,35.56 218.44,51.44 SV2.26 | 208.28,35.56 208.28,20.96 206.38,19.05 206.38,13.97 U$6.U1
  pour Bottom (isolate 0.254): 260.35,125.73 260.35,13.97 0,13.97 0,125.73
  pour Top (isolate 0.254): 260.35,13.97 260.35,125.73 0,125.73 0,13.97
H3
  Top 0.381: SV2.12 236.22,51.44 236.22,34.93 237.49,33.66 SV6.R
  Bottom 0.381: SV6.R 237.49,32.39 237.49,13.97 U$6.H2
H4
  Top 0.381: U$6.H1 236.22,13.97 236.22,31.12 234.95,32.39 SV6.T
  Bottom 0.381: SV5.16 229.87,85.73 229.87,40.01 233.68,36.2 233.68,34.93 234.95,33.66 SV6.T
H5
  Top 0.381: SV7.12 170.18,51.44 170.18,34.93 171.45,33.66 SV9.R
  Bottom 0.381: SV9.R 171.45,32.39 171.45,13.97 U$10.H2
H6
  Top 0.381: U$10.H1 170.18,13.97 170.18,31.12 168.91,32.39 SV9.T
  Bottom 0.381: SV8.16 163.83,85.73 163.83,40.01 167.64,36.2 167.64,34.93 168.91,33.66 SV9.T
H7
  Top 0.381: SV10.12 104.14,51.44 104.14,34.93 105.41,33.66 SV12.R
  Bottom 0.381: SV12.R 105.41,32.39 105.41,13.97 U$14.H2
H8
  Top 0.381: U$14.H1 104.14,13.97 104.14,31.12 102.87,32.39 SV12.T
  Bottom 0.381: SV11.16 97.79,85.73 97.79,40.01 101.6,36.2 101.6,34.93 102.87,33.66 SV12.T
H9
  Top 0.381: SV13.12 38.1,51.44 38.1,34.93 39.37,33.66 SV15.R
  Bottom 0.381: SV15.R 39.37,32.39 39.37,13.97 U$18.H2
H10
  Top 0.381: U$18.H1 38.1,13.97 38.1,31.12 36.83,32.39 SV15.T
  Bottom 0.381: SV14.16 31.75,85.73 31.75,40.01 35.56,36.2 35.56,34.93 36.83,33.66 SV15.T
J2
  Top 0.381: U$6.J1 233.04,13.97 233.04,29.21 229.87,32.39 SV6.X
  Bottom 0.381: SV5.20 224.79,85.73 224.79,40.01 228.6,36.2 228.6,34.93 229.87,33.66 SV6.X
J3
  Top 0.381: U$10.J1 167,13.97 167,29.21 163.83,32.39 SV9.X
  Bottom 0.381: SV8.20 158.75,85.73 158.75,40.01 162.56,36.2 162.56,34.93 163.83,33.66 SV9.X
J4
  Top 0.381: U$14.J1 100.97,13.97 100.97,29.21 97.79,32.39 SV12.X
  Bottom 0.381: SV11.20 92.71,85.73 92.71,40.01 96.52,36.2 96.52,34.93 97.79,33.66 SV12.X
J5
  Top 0.381: U$18.J1 34.92,13.97 34.92,29.21 31.75,32.39 SV15.X
  Bottom 0.381: SV14.20 26.67,85.73 26.67,40.01 30.48,36.2 30.48,34.93 31.75,33.66 SV15.X
K1
  Top 0.381: SV2.16 231.14,51.44 231.14,34.93 232.41,33.66 SV6.V
  Bottom 0.381: SV6.V 232.41,32.39 232.41,14.61 231.78,13.97 U$6.K2
K3
  Top 0.381: SV7.16 165.1,51.44 165.1,34.93 166.37,33.66 SV9.V
  Bottom 0.381: SV9.V 166.37,32.39 166.37,14.61 165.74,13.97 U$10.K2
K4
  Top 0.381: SV10.16 99.06,51.44 99.06,34.93 100.33,33.66 SV12.V
  Bottom 0.381: SV12.V 100.33,32.39 100.33,14.61 99.69,13.97 U$14.K2
K5
  Top 0.381: SV13.16 33.02,51.44 33.02,34.93 34.29,33.66 SV15.V
  Bottom 0.381: SV15.V 34.29,32.39 34.29,14.61 33.66,13.97 U$18.K2
L2
  Top 0.381: U$6.L1 226.69,13.97 226.69,30.48 224.79,32.39 SV6.BB
  Bottom 0.381: SV5.24 219.71,85.73 219.71,40.01 223.52,36.2 223.52,34.93 224.79,33.66 SV6.BB
L3
  Top 0.381: U$10.L1 160.66,13.97 160.66,30.48 158.75,32.39 SV9.BB
  Bottom 0.381: SV8.24 153.67,85.73 153.67,40.01 157.48,36.2 157.48,34.93 158.75,33.66 SV9.BB
L4
  Top 0.381: U$14.L1 94.61,13.97 94.61,30.48 92.71,32.39 SV12.BB
  Bottom 0.381: SV11.24 87.63,85.73 87.63,40.01 91.44,36.2 91.44,34.93 92.71,33.66 SV12.BB
L5
  Top 0.381: U$18.L1 28.57,13.97 28.57,30.48 26.67,32.39 SV15.BB
  Bottom 0.381: SV14.24 21.59,85.73 21.59,40.01 25.4,36.2 25.4,34.93 26.67,33.66 SV15.BB
M3
  Top 0.381: SV2.20 226.06,51.44 226.06,34.93 227.33,33.66 SV6.Z
  Bottom 0.381: SV6.Z 227.33,32.39 227.33,16.51 224.79,13.97 U$6.M2
M4
  Top 0.381: SV5.28 214.63,85.73 214.63,40.01 218.44,36.2 218.44,34.93 219.71,33.66 SV6.FF 219.71,32.39 223.52,28.58 223.52,13.97 U$6.M1
M5
  Top 0.381: SV7.20 160.02,51.44 160.02,34.93 161.29,33.66 SV9.Z
  Bottom 0.381: SV9.Z 161.29,32.39 161.29,16.51 158.75,13.97 U$10.M2
M6
  Top 0.381: SV8.28 148.59,85.73 148.59,40.01 152.4,36.2 152.4,34.93 153.67,33.66 SV9.FF 153.67,32.39 157.48,28.58 157.48,13.97 U$10.M1
M7
  Top 0.381: SV10.20 93.98,51.44 93.98,34.93 95.25,33.66 SV12.Z
  Bottom 0.381: SV12.Z 95.25,32.39 95.25,16.51 92.71,13.97 U$14.M2
M8
  Top 0.381: SV11.28 82.55,85.73 82.55,40.01 86.36,36.2 86.36,34.93 87.63,33.66 SV12.FF 87.63,32.39 91.44,28.58 91.44,13.97 U$14.M1
M9
  Top 0.381: SV13.20 27.94,51.44 27.94,34.93 29.21,33.66 SV15.Z
  Bottom 0.381: SV15.Z 29.21,32.39 29.21,16.51 26.67,13.97 U$18.M2
M10
  Top 0.381: SV14.28 16.51,85.73 16.51,40.01 20.32,36.2 20.32,34.93 21.59,33.66 SV15.FF 21.59,32.39 25.4,28.58 25.4,13.97 U$18.M1
P3
  Top 0.381: SV2.24 220.98,51.44 220.98,34.93 222.25,33.66 SV6.DD
  Bottom 0.381: SV6.DD 222.25,32.39 222.25,17.78 218.44,13.97 U$6.P2
P4
  Top 0.381: SV5.30 212.09,85.73 212.09,37.47 213.36,36.2 213.36,34.93 214.63,33.66 SV6.LL 214.63,32.39 217.17,29.85 217.17,13.97 U$6.P1
P5
  Top 0.381: SV7.24 154.94,51.44 154.94,34.93 156.21,33.66 SV9.DD
  Bottom 0.381: SV9.DD 156.21,32.39 156.21,17.78 152.4,13.97 U$10.P2
P6
  Top 0.381: SV8.30 146.05,85.73 146.05,37.47 147.32,36.2 147.32,34.93 148.59,33.66 SV9.LL 148.59,32.39 151.13,29.85 151.13,13.97 U$10.P1
P7
  Top 0.381: SV10.24 88.9,51.44 88.9,34.93 90.17,33.66 SV12.DD
  Bottom 0.381: SV12.DD 90.17,32.39 90.17,17.78 86.36,13.97 U$14.P2
P8
  Top 0.381: SV11.30 80.01,85.73 80.01,37.47 81.28,36.2 81.28,34.93 82.55,33.66 SV12.LL 82.55,32.39 85.09,29.85 85.09,13.97 U$14.P1
P9
  Top 0.381: SV13.24 22.86,51.44 22.86,34.93 24.13,33.66 SV15.DD
  Bottom 0.381: SV15.DD 24.13,32.39 24.13,17.78 20.32,13.97 U$18.P2
P10
  Top 0.381: SV14.30 13.97,85.73 13.97,37.47 15.24,36.2 15.24,34.93 16.51,33.66 SV15.LL 16.51,32.39 19.05,29.85 19.05,13.97 U$18.P1
S3
  Bottom 0.381: SV2.28 215.9,51.44 215.9,34.93 217.17,33.66 SV6.JJ 217.17,32.39 217.17,19.05 212.09,13.97 U$6.S2
S4
  Top 0.381: U$6.S1 210.82,13.97 210.82,31.12 209.55,32.39 SV6.RR
  Bottom 0.381: SV5.32 209.55,85.73 209.55,37.47 210.82,36.2 210.82,34.93 209.55,33.66 SV6.RR
S5
  Bottom 0.381: SV7.28 149.86,51.44 149.86,34.93 151.13,33.66 SV9.JJ 151.13,32.39 151.13,19.05 146.05,13.97 U$10.S2
S6
  Top 0.381: U$10.S1 144.78,13.97 144.78,31.12 143.51,32.39 SV9.RR
  Bottom 0.381: SV8.32 143.51,85.73 143.51,37.47 144.78,36.2 144.78,34.93 143.51,33.66 SV9.RR
S7
  Bottom 0.381: SV10.28 83.82,51.44 83.82,34.93 85.09,33.66 SV12.JJ 85.09,32.39 85.09,19.05 80.01,13.97 U$14.S2
S8
  Top 0.381: U$14.S1 78.74,13.97 78.74,31.12 77.47,32.39 SV12.RR
  Bottom 0.381: SV11.32 77.47,85.73 77.47,37.47 78.74,36.2 78.74,34.93 77.47,33.66 SV12.RR
S9
  Bottom 0.381: SV13.28 17.78,51.44 17.78,34.93 19.05,33.66 SV15.JJ 19.05,32.39 19.05,19.05 13.97,13.97 U$18.S2
S10
  Top 0.381: U$18.S1 12.7,13.97 12.7,31.12 11.43,32.39 SV15.RR
  Bottom 0.381: SV14.32 11.43,85.73 11.43,37.47 12.7,36.2 12.7,34.93 11.43,33.66 SV15.RR
T1
  Bottom 0.381: SV2.30 213.36,51.44 213.36,34.93 212.09,33.66 SV6.NN 212.09,32.39 212.09,17.15 208.91,13.97 U$6.T2
T3
  Bottom 0.381: SV7.30 147.32,51.44 147.32,34.93 146.05,33.66 SV9.NN 146.05,32.39 146.05,17.15 142.88,13.97 U$10.T2
T4
  Bottom 0.381: SV10.30 81.28,51.44 81.28,34.93 80.01,33.66 SV12.NN 80.01,32.39 80.01,17.15 76.83,13.97 U$14.T2
T5
  Bottom 0.381: SV13.30 15.24,51.44 15.24,34.93 13.97,33.66 SV15.NN 13.97,32.39 13.97,17.15 10.79,13.97 U$18.T2
V1
  Top 0.381: SV2.32 210.82,51.44 210.82,38.74 208.28,36.2 208.28,34.93 207.01,33.66 SV6.TT
  Bottom 0.381: SV6.TT 207.01,32.39 207.01,20.96 203.2,17.15 203.2,13.97 U$6.V2
V3
  Top 0.381: SV7.32 144.78,51.44 144.78,38.74 142.24,36.2 142.24,34.93 140.97,33.66 SV9.TT
  Bottom 0.381: SV9.TT 140.97,32.39 140.97,20.96 137.16,17.15 137.16,13.97 U$10.V2
V4
  Top 0.381: SV10.32 78.74,51.44 78.74,38.74 76.2,36.2 76.2,34.93 74.93,33.66 SV12.TT
  Bottom 0.381: SV12.TT 74.93,32.39 74.93,20.96 71.12,17.15 71.12,13.97 U$14.V2
V5
  Top 0.381: SV13.32 12.7,51.44 12.7,38.74 10.16,36.2 10.16,34.93 8.89,33.66 SV15.TT
  Bottom 0.381: SV15.TT 8.89,32.39 8.89,20.96 5.08,17.15 5.08,13.97 U$18.V2

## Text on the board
Top: BC08J/Negibus/Posibus | BC08J/Negibus/Posibus | BC08J/Negibus/Posibus | BC08J/Negibus/Posibus
Bottom: BC08J/Negibus/Posibus | BC08J/Negibus/Posibus | BC08J/Negibus/Posibus | BC08J/Negibus/Posibus
tPlace: BC08J/Negibus/Posibus | BC08J/Negibus/Posibus | BC08J/Negibus/Posibus | BC08J/Negibus/Posibus
tValues: * | * | * | * | * | * | * | * | * | * | * | * | * | * | * | * | * | * | * | * | * | * | * | * | * | * | * | * | * | * | * | * | * | * | * | * | Side 1 | Side 1 | Side 1 | Side 1 | * | * | * | * | * | * | * | * | * | * | * | * | * | * | * | * | * | * | * | * | * | * | * | * | * | * | * | * | * | * | * | * | * | * | * | * | Side 2 | Side 2 | Side 2 | Side 2 | * | * | * | * | * | * | * | * | * | * | * | * | * | * | * | * | * | * | * | * | * | * | * | * | * | * | * | * | * | * | * | * | * | * | * | * | * | * | * | * | * | * | * | * | * | * | * | * | * | * | * | * | * | * | * | * | * | * | * | * | * | * | * | * | * | * | * | * | * | * | * | * | BC08J | BC08J | BC08J | BC08J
